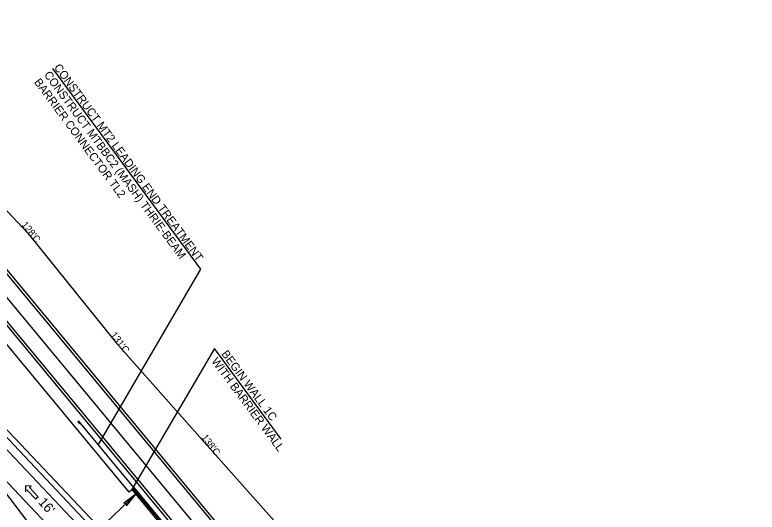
# Model space of a CAD drawing. Extents: x 1966090 to 1975830, y 788086 to 801233.
# Drawn here: x 1970542 to 1971083, y 797102 to 797464 of the extents above; entities that cross this region are included whole.
import ezdxf

# ---------------------------------------------------------------- set-up
doc = ezdxf.new("R2010")
doc.units = 0
for name, color, linetype in [('BR_PRESTRESSED BEAM', 7, 'Continuous'), ('BR_PROPOSED_DRAINAGE', 7, 'Continuous'), ('BR_REBAR', 7, 'Continuous'), ('RD_EX_Driveway_txCode', 7, 'Continuous'), ('RD_EX_RW_TX', 7, 'Continuous'), ('RD_EX_Survey_Limits', 7, 'Continuous'), ('RD_EX_TX_Dam_ELEV', 7, 'Continuous'), ('RD_PD_PaveShd', 7, 'Continuous'), ('RD_Sketch6', 7, 'Continuous'), ('RD_Sketch8', 7, 'Continuous')]:
    doc.layers.add(name, color=color, linetype=linetype)

msp = doc.modelspace()

# ---------------------------------------------------------------- linework, layer by layer
at = {"layer": 'BR_PRESTRESSED BEAM'}
for p, q in [((1970340.58, 797367.47), (1970655.12, 797035.82)), ((1970588.15, 797168.18), (1970587.38, 797167.54)), ((1970614.97, 797135.85), (1970588.15, 797168.18)), ((1970589.43, 797166.64), (1970588.15, 797168.18)), ((1970587.38, 797167.54), (1970588.85, 797166.16)), ((1970588.85, 797166.16), (1970589.43, 797166.64)), ((1970628.53, 797119.5), (1970614.97, 797135.85))]:
    msp.add_line(p, q, dxfattribs=at)
at = {"layer": 'BR_PROPOSED_DRAINAGE'}
for p, q in [((1970477.86, 797382.4), (1970550.94, 797305.27)), ((1970550.94, 797305.27), (1970615.52, 797225.13)), ((1970615.52, 797225.13), (1970682.04, 797150.08)), ((1970682.04, 797150.08), (1970748.85, 797075.26))]:
    msp.add_line(p, q, dxfattribs=at)
at = {"layer": 'BR_REBAR'}
for p, q in [((1970628.53, 797119.5), (1970626.99, 797118.22)), ((1970628.53, 797119.5), (1970965.07, 796713.78)), ((1970626.99, 797118.22), (1970963.53, 796712.5))]:
    msp.add_line(p, q, dxfattribs=at)
at = {"layer": 'RD_EX_Driveway_txCode'}
msp.add_lwpolyline([(1970556.74, 797111.34), (1970558.48, 797112.99), (1970552.17, 797119.65), (1970553.36, 797120.77), (1970549.36, 797120.88), (1970549.25, 797116.88), (1970550.43, 797118)], close=True, dxfattribs=at)
at = {"layer": 'RD_EX_Survey_Limits'}
msp.add_line((1970371.42, 797456.09), (1970870.17, 796854.82), dxfattribs=at)
at = {"layer": 'RD_EX_TX_Dam_ELEV'}
for p, q in [((1970354.49, 797442.04), (1970624.68, 797116.3)), ((1970627.76, 797118.86), (1970624.68, 797116.3)), ((1970627.76, 797118.86), (1970899.28, 796791.53))]:
    msp.add_line(p, q, dxfattribs=at)
at = {"layer": 'RD_PD_PaveShd'}
for p, q in [((1970381.42, 797464.39), (1970880.17, 796863.12)), ((1970361.41, 797447.79), (1970860.16, 796846.52)), ((1970337.68, 797364.72), (1970967.22, 796700.93))]:
    msp.add_line(p, q, dxfattribs=at)
at = {"layer": 'RD_Sketch6'}
for p, q in [((1970568.91, 797425.38), (1970676.95, 797278.83)), ((1970676.95, 797278.83), (1970602.24, 797151.19)), ((1970687.16, 797221), (1970626.99, 797118.22)), ((1970735.87, 797154.93), (1970687.16, 797221)), ((1970600.87, 797087.33), (1970629.83, 797114.8)), ((1970629.83, 797114.8), (1970620.97, 797108.32)), ((1970622.91, 797106.29), (1970629.83, 797114.8)), ((1970620.97, 797108.32), (1970622.71, 797108.04)), ((1970622.71, 797108.04), (1970622.91, 797106.29))]:
    msp.add_line(p, q, dxfattribs=at)
at = {"layer": 'RD_Sketch8'}
for p, q in [((1970379.89, 797463.11), (1970878.63, 796861.84)), ((1970362.95, 797449.06), (1970861.7, 796847.8)), ((1970333.32, 797360.59), (1970962.87, 796696.8)), ((1970499.5, 797162.12), (1970951.26, 796685.79)), ((1970499.5, 797162.12), (1971082.9, 796393.86))]:
    msp.add_line(p, q, dxfattribs=at)

# ---------------------------------------------------------------- texts
at = {"layer": 'RD_EX_Driveway_txCode'}
msp.add_text("16'", height=7, rotation=311.6774, dxfattribs=at).set_placement((1970558.24, 797108.61))
at = {"layer": 'RD_EX_RW_TX'}
for s, rotation, p in [("128'C", 308.5012, (1970546.17, 797311.27)), ("131'C", 307.212, (1970611.17, 797230.86)), ("138'C", 307.212, (1970677.4, 797156.19))]:
    msp.add_text(s, height=5, rotation=rotation, dxfattribs=at).set_placement(p)
at = {"layer": 'RD_Sketch6'}
for s, rotation, p in [('CONSTRUCT MT2 LEADING END TREATMENT', 306.4243, (1970569.77, 797425.97)), ('CONSTRUCT MTBBC2 (MASH) THRIE-BEAM', 306.4243, (1970562.52, 797420.62)), ('BARRIER CONNECTOR TL2', 306.4243, (1970555.28, 797415.28)), ('BEGIN WALL 1C', 306.5574, (1970691.81, 797217.06)), ('WITH BARRIER WALL', 306.5574, (1970684.58, 797211.7))]:
    msp.add_text(s, height=5.9996, rotation=rotation, dxfattribs=at).set_placement(p)

doc.saveas('drawing.dxf')
